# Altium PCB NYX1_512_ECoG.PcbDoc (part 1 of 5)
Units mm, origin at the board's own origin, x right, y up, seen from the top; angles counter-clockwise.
Board outline 46.64 x 13 mm, 4 copper layers (metal 2, via, metal1, electrodes), stack 0.007 mm thick; 9 components, 547 nets, 1871 pads, 0 vias.
Unrouted connection lines stored in the file: 652.
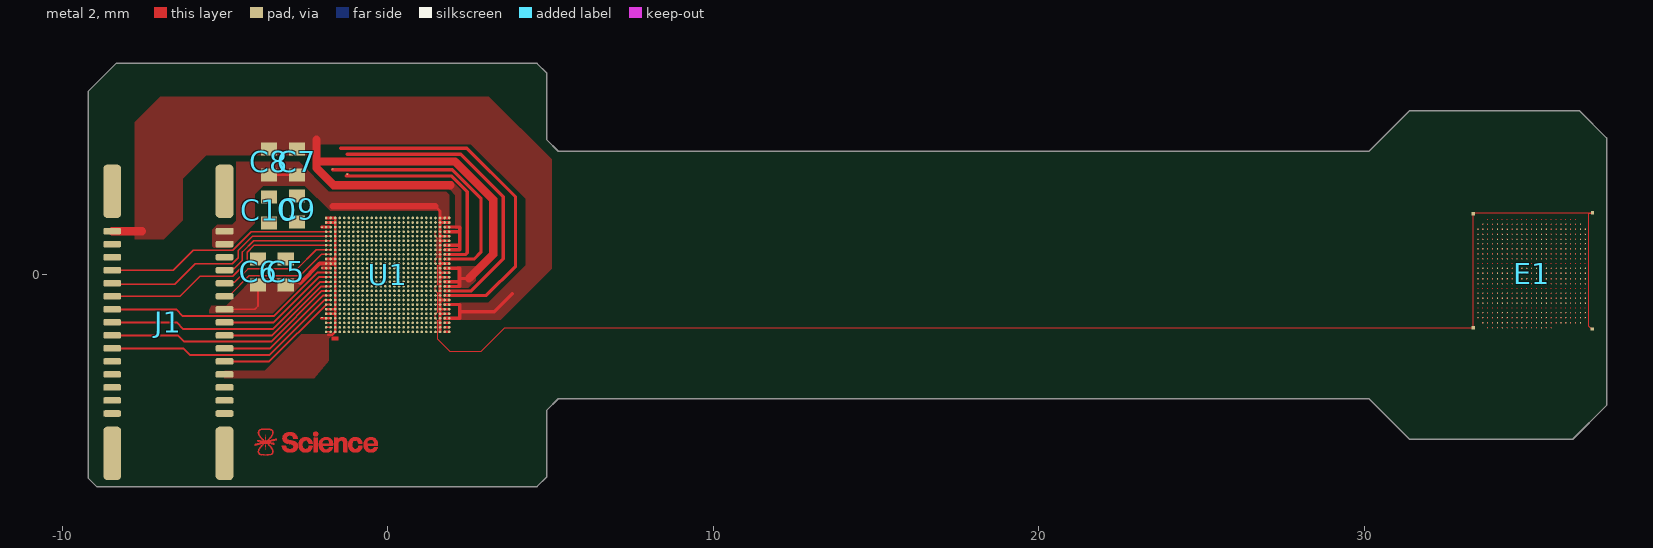
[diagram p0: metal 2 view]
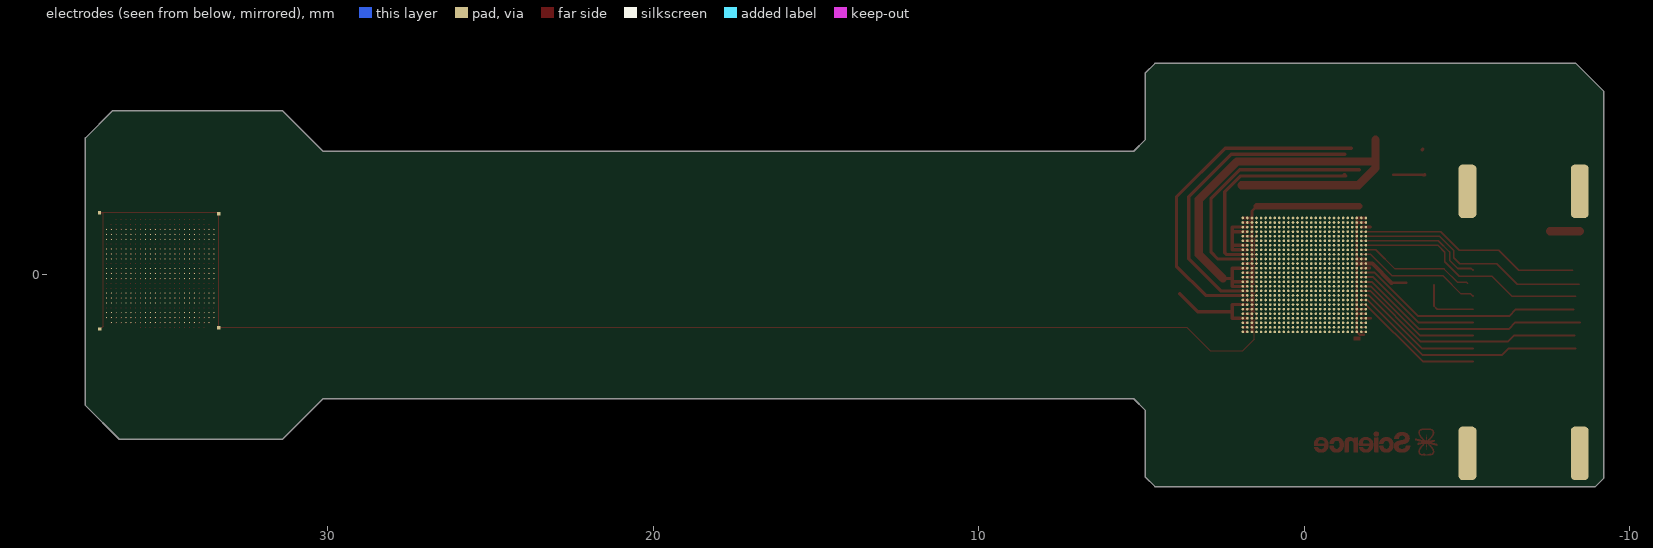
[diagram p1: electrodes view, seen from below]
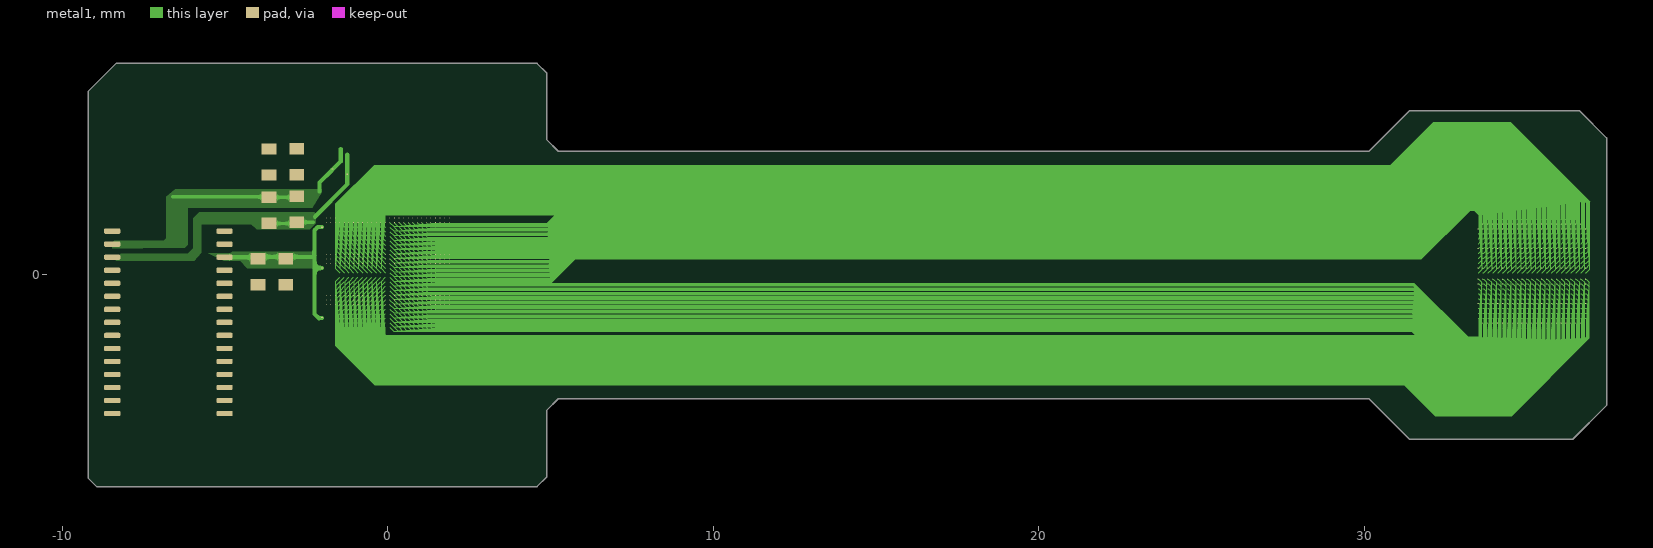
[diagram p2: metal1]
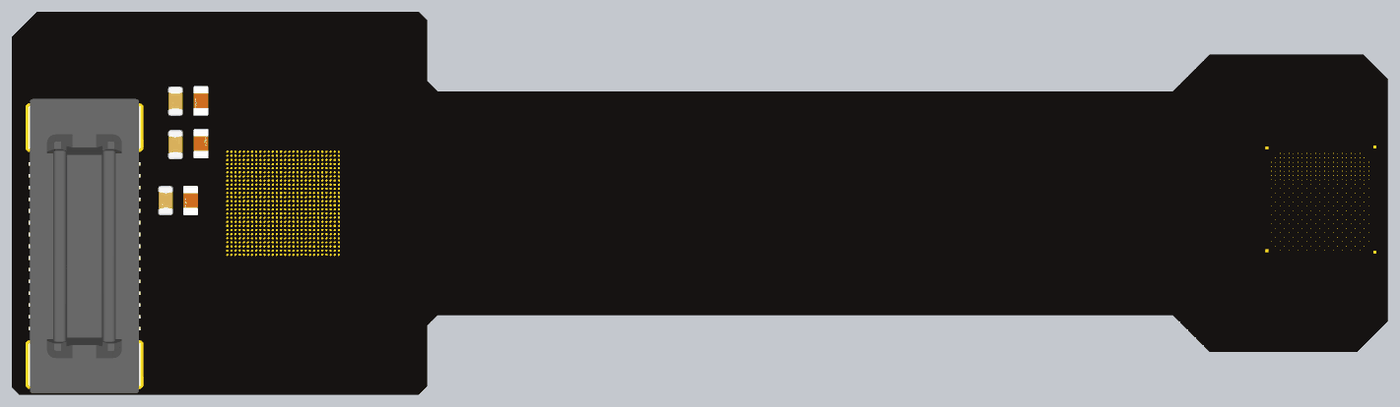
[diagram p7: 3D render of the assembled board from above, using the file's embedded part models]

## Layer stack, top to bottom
Top Solder: solder mask 0.003, Solder Resist, Dk 3.5
metal 2: signal copper 0.0002
Dielectric 2: prepreg 0.003, PP-006, Dk 4
via: signal copper 0.0002
Dielectric 1: dielectric 0.0001, FR-4, Dk 4
metal1: signal copper 0.0002
Dielectric 3: prepreg 0.003, PP-006, Dk 4
electrodes: signal copper 0.0002
Bottom Solder: solder mask 0.003, Solder Resist, Dk 3.5

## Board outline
-9.2,-6.239 -8.939,-6.5 4.592,-6.5 4.88,-6.212 4.88,-4.161 5.241,-3.8 30.141,-3.8 31.388,-5.047 36.4,-5.047 37.441,-4.006 37.441,4.21 36.604,5.047 31.388,5.047 30.141,3.8 5.241,3.8 4.88,4.161 4.88,6.212 4.592,6.5 -8.339,6.5 -9.2,5.639

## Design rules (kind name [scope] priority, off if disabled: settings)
BoardOutlineClearance [All] p1: gap=0.2 ignorepadtopadclearanceinfootprint=FALSE except(0: Arc-SplitContinuation Track-SplitContinuation SMDPad-SplitContinuation THPad-SplitContinuation Via-SplitContinuation Fill-SplitContinuation Poly-SplitContinuation Region-SplitContinuation Text-SplitContinuation)
Clearance [All] p1: gap=0.005 ignorepadtopadclearanceinfootprint=FALSE
ComponentClearance [All] p1: gap=0.254 collisioncheckmode=3 verticalgap=0.254 showdistances=FALSE donotcheckwithout3dbody=TRUE
MinimumSolderMaskSliver [All] p1: minsoldermaskwidth=0
PolygonConnect [All] p1: connectstyle=Direct reliefconductorwidth=0.254 reliefentries=4 polygonreliefangle="90 Angle" airgapwidth=0.254
RoutingVias [All] p1: holewidth=0.711 width=1.27 viastyle="Through Hole" minholewidth=0.711 minwidth=1.27 maxholewidth=0.711 maxwidth=1.27
SilkToSolderMaskClearance [IsPad] p1: minsilkscreentomaskgap=0 clearancetoexposedcopper=TRUE
SolderMaskExpansion [All] p1: expansion=0.102 istentingtop=FALSE
SupplyNets "Schematic Supply Nets_2" [InNet('DVSS')] p1: voltage=0.000
SupplyNets "Schematic Supply Nets_1" [InNet('DVSS_BOT')] p2: voltage=0.000
SupplyNets "Schematic Supply Nets" [InNet('VSSA')] p3: voltage=0.000
Width [All] p1: maxlimit=0.254 minlimit=0.005 preferedwidth=0.254 minimp=50.000000 maximp=50.000000 favimp=50.000000
27 further rules are at their usual default settings.

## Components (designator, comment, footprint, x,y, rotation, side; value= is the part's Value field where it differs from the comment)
C5 "GRT155R61E105KE01D" FP-GRT155-0_05-MFG -3.13,0.095 r270 top
C6 "CC0402KRX7R9BB104" FP-CC0402-MFG -3.98,0.095 r270 top value="100 nF"
C7 "GRT155R61E105KE01D" FP-GRT155-0_05-MFG -2.786,3.476 r270 top
C8 "CC0402KRX7R9BB104" FP-CC0402-MFG -3.644,3.47 r270 top value="100 nF"
C9 "GRT155R61E105KE01D" FP-GRT155-0_05-MFG -2.786,2.021 r90 top
C10 "CC0402KRX7R9BB104" FP-CC0402-MFG -3.644,1.992 r90 top value="100 nF"
E1 "512 Electrode Array MEA Layout" "512 Electrode Array-Footprint-1" 33.491,1.694 r0 top locked
J1 "BM54F3.0-30DP-0.4V_51_" BM54F3030DP04V51 -6.734,-1.454 r270 top locked
U1 "NYX512" NYX512_footprint 0,0.001 r270 top

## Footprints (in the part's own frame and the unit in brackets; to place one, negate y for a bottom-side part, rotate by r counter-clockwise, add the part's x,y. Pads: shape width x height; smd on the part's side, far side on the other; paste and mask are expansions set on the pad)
"512 Electrode Array-Footprint-1" [mm]
  rect 0.02x0.02 / inner rect 0x0 / far side rect 0.02x0.02 all layers, no hole mask-0.002: 1(0.3,0) 2(0.45,0) 3(0.6,0) 4(0.75,0) 5(0.9,0) 6(1.05,0) 7(1.2,0) 8(1.35,0) 9(1.5,0) 10(1.65,0) 11(1.8,0) 12(1.95,0) 13(2.1,0) 14(2.25,0) 15(2.4,0) 16(2.55,0) 17(2.7,0) 18(2.85,0) 19(3,0) 20(0.15,-0.15) 21(0.3,-0.15) 22(0.45,-0.15) 23(0.6,-0.15) 24(0.75,-0.15) 25(0.9,-0.15) 26(1.05,-0.15) 27(1.2,-0.15) 28(1.35,-0.15) 29(1.5,-0.15) 30(1.65,-0.15) 31(1.8,-0.15) 32(1.95,-0.15) 33(2.1,-0.15) 34(2.25,-0.15) 35(2.4,-0.15) 36(2.55,-0.15) 37(2.7,-0.15) 38(2.85,-0.15) 39(3,-0.15) 40(3.15,-0.15) 41(0,-0.3) 42(0.15,-0.3) 43(0.3,-0.3) 44(0.45,-0.3) 45(0.6,-0.3) 46(0.75,-0.3) 47(0.9,-0.3) 48(1.05,-0.3) 49(1.2,-0.3) 50(1.35,-0.3) 51(1.5,-0.3) 52(1.65,-0.3) 53(1.8,-0.3) 54(1.95,-0.3) 55(2.1,-0.3) 56(2.25,-0.3) 57(2.4,-0.3) 58(2.55,-0.3) 59(2.7,-0.3) 60(2.85,-0.3) 61(3,-0.3) 62(3.15,-0.3) 63(3.3,-0.3) 64(0,-0.45) 65(0.15,-0.45) 66(0.3,-0.45) 67(0.45,-0.45) 68(0.6,-0.45) 69(0.75,-0.45) 70(0.9,-0.45) 71(1.05,-0.45) 72(1.2,-0.45) 73(1.35,-0.45) 74(1.5,-0.45) 75(1.65,-0.45) 76(1.8,-0.45) 77(1.95,-0.45) 78(2.1,-0.45) 79(2.25,-0.45) 80(2.4,-0.45) 81(2.55,-0.45) 82(2.7,-0.45) 83(2.85,-0.45) 84(3,-0.45) 85(3.15,-0.45) 86(3.3,-0.45) 87(0,-0.6) 88(0.15,-0.6) 89(0.3,-0.6) 90(0.45,-0.6) 91(0.6,-0.6) 92(0.75,-0.6) 93(0.9,-0.6) 94(1.05,-0.6) 95(1.2,-0.6) 96(1.35,-0.6) 97(1.5,-0.6) 98(1.65,-0.6) 99(1.8,-0.6) 100(1.95,-0.6) 101(2.1,-0.6) 102(2.25,-0.6) 103(2.4,-0.6) 104(2.55,-0.6) 105(2.7,-0.6) 106(2.85,-0.6) 107(3,-0.6) 108(3.15,-0.6) 109(3.3,-0.6) 110(0,-0.75) 111(0.15,-0.75) 112(0.3,-0.75) 113(0.45,-0.75) 114(0.6,-0.75) 115(0.75,-0.75) 116(0.9,-0.75) 117(1.05,-0.75) 118(1.2,-0.75) 119(1.35,-0.75) 120(1.5,-0.75) 121(1.65,-0.75) 122(1.8,-0.75) 123(1.95,-0.75) 124(2.1,-0.75) 125(2.25,-0.75) 126(2.4,-0.75) 127(2.55,-0.75) 128(2.7,-0.75) 129(2.85,-0.75) 130(3,-0.75) 131(3.15,-0.75) 132(3.3,-0.75) 133(0,-0.9) 134(0.15,-0.9) 135(0.3,-0.9) 136(0.45,-0.9) 137(0.6,-0.9) 138(0.75,-0.9) 139(0.9,-0.9) 140(1.05,-0.9) 141(1.2,-0.9) 142(1.35,-0.9) 143(1.5,-0.9) 144(1.65,-0.9) 145(1.8,-0.9) 146(1.95,-0.9) 147(2.1,-0.9) 148(2.25,-0.9) 149(2.4,-0.9) 150(2.55,-0.9) 151(2.7,-0.9) 152(2.85,-0.9) 153(3,-0.9) 154(3.15,-0.9) 155(3.3,-0.9) 156(0,-1.05) 157(0.15,-1.05) 158(0.3,-1.05) 159(0.45,-1.05) 160(0.6,-1.05) 161(0.75,-1.05) 162(0.9,-1.05) 163(1.05,-1.05) 164(1.2,-1.05) 165(1.35,-1.05) 166(1.5,-1.05) 167(1.65,-1.05) 168(1.8,-1.05) 169(1.95,-1.05) 170(2.1,-1.05) 171(2.25,-1.05) 172(2.4,-1.05) 173(2.55,-1.05) 174(2.7,-1.05) 175(2.85,-1.05) 176(3,-1.05) 177(3.15,-1.05) 178(3.3,-1.05) 179(0,-1.2) 180(0.15,-1.2) 181(0.3,-1.2) 182(0.45,-1.2) 183(0.6,-1.2) 184(0.75,-1.2) 185(0.9,-1.2) 186(1.05,-1.2) 187(1.2,-1.2) 188(1.35,-1.2) 189(1.5,-1.2) 190(1.65,-1.2) 191(1.8,-1.2) 192(1.95,-1.2) 193(2.1,-1.2) 194(2.25,-1.2) 195(2.4,-1.2) 196(2.55,-1.2) 197(2.7,-1.2) 198(2.85,-1.2) 199(3,-1.2) 200(3.15,-1.2) 201(3.3,-1.2) 202(0,-1.35) 203(0.15,-1.35) 204(0.3,-1.35) 205(0.45,-1.35) 206(0.6,-1.35) 207(0.75,-1.35) 208(0.9,-1.35) 209(1.05,-1.35) 210(1.2,-1.35) 211(1.35,-1.35) 212(1.5,-1.35) 213(1.65,-1.35) 214(1.8,-1.35) 215(1.95,-1.35) 216(2.1,-1.35) 217(2.25,-1.35) 218(2.4,-1.35) 219(2.55,-1.35) 220(2.7,-1.35) 221(2.85,-1.35) 222(3,-1.35) 223(3.15,-1.35) 224(3.3,-1.35) 225(0,-1.5) 226(0.15,-1.5) 227(0.3,-1.5) 228(0.45,-1.5) 229(0.6,-1.5) 230(0.75,-1.5) 231(0.9,-1.5) 232(1.05,-1.5) 233(1.2,-1.5) 234(1.35,-1.5) 235(1.5,-1.5) 236(1.65,-1.5) 237(1.8,-1.5) 238(1.95,-1.5) 239(2.1,-1.5) 240(2.25,-1.5) 241(2.4,-1.5) 242(2.55,-1.5) 243(2.7,-1.5) 244(2.85,-1.5) 245(3,-1.5) 246(3.15,-1.5) 247(3.3,-1.5) 248(0,-1.65) 249(0.15,-1.65) 250(0.3,-1.65) 251(0.45,-1.65) 252(0.6,-1.65) 253(0.75,-1.65) 254(0.9,-1.65) 255(1.05,-1.65) 256(1.2,-1.65) 257(1.35,-1.65) 258(1.5,-1.65) 259(1.65,-1.65) 260(1.8,-1.65) 261(1.95,-1.65) 262(2.1,-1.65) 263(2.25,-1.65) 264(2.4,-1.65) 265(2.55,-1.65) 266(2.7,-1.65) 267(2.85,-1.65) 268(3,-1.65) 269(3.15,-1.65) 270(3.3,-1.65) 271(0,-1.8) 272(0.15,-1.8) 273(0.3,-1.8) 274(0.45,-1.8) 275(0.6,-1.8) 276(0.75,-1.8) 277(0.9,-1.8) 278(1.05,-1.8) 279(1.2,-1.8) 280(1.35,-1.8) 281(1.5,-1.8) 282(1.65,-1.8) 283(1.8,-1.8) 284(1.95,-1.8) 285(2.1,-1.8) 286(2.25,-1.8) 287(2.4,-1.8) 288(2.55,-1.8) 289(2.7,-1.8) 290(2.85,-1.8) 291(3,-1.8) 292(3.15,-1.8) 293(3.3,-1.8) 294(0,-1.95) 295(0.15,-1.95) 296(0.3,-1.95) 297(0.45,-1.95) 298(0.6,-1.95) 299(0.75,-1.95) 300(0.9,-1.95) 301(1.05,-1.95) 302(1.2,-1.95) 303(1.35,-1.95) 304(1.5,-1.95) 305(1.65,-1.95) 306(1.8,-1.95) 307(1.95,-1.95) 308(2.1,-1.95) 309(2.25,-1.95) 310(2.4,-1.95) 311(2.55,-1.95) 312(2.7,-1.95) 313(2.85,-1.95) 314(3,-1.95) 315(3.15,-1.95) 316(3.3,-1.95) 317(0,-2.1) 318(0.15,-2.1) 319(0.3,-2.1) 320(0.45,-2.1) 321(0.6,-2.1) 322(0.75,-2.1) 323(0.9,-2.1) 324(1.05,-2.1) 325(1.2,-2.1) 326(1.35,-2.1) 327(1.5,-2.1) 328(1.65,-2.1) 329(1.8,-2.1) 330(1.95,-2.1) 331(2.1,-2.1) 332(2.25,-2.1) 333(2.4,-2.1) 334(2.55,-2.1) 335(2.7,-2.1) 336(2.85,-2.1) 337(3,-2.1) 338(3.15,-2.1) 339(3.3,-2.1) 340(0,-2.25) 341(0.15,-2.25) 342(0.3,-2.25) 343(0.45,-2.25) 344(0.6,-2.25) 345(0.75,-2.25) 346(0.9,-2.25) 347(1.05,-2.25) 348(1.2,-2.25) 349(1.35,-2.25) 350(1.5,-2.25) 351(1.65,-2.25) 352(1.8,-2.25) 353(1.95,-2.25) 354(2.1,-2.25) 355(2.25,-2.25) 356(2.4,-2.25) 357(2.55,-2.25) 358(2.7,-2.25) 359(2.85,-2.25) 360(3,-2.25) 361(3.15,-2.25) 362(3.3,-2.25) 363(0,-2.4) 364(0.15,-2.4) 365(0.3,-2.4) 366(0.45,-2.4) 367(0.6,-2.4) 368(0.75,-2.4) 369(0.9,-2.4) 370(1.05,-2.4) 371(1.2,-2.4) 372(1.35,-2.4) 373(1.5,-2.4) 374(1.65,-2.4) 375(1.8,-2.4) 376(1.95,-2.4) 377(2.1,-2.4) 378(2.25,-2.4) 379(2.4,-2.4) 380(2.55,-2.4) 381(2.7,-2.4) 382(2.85,-2.4) 383(3,-2.4) 384(3.15,-2.4) 385(3.3,-2.4) 386(0,-2.55) 387(0.15,-2.55) 388(0.3,-2.55) 389(0.45,-2.55) 390(0.6,-2.55) 391(0.75,-2.55) 392(0.9,-2.55) 393(1.05,-2.55) 394(1.2,-2.55) 395(1.35,-2.55) 396(1.5,-2.55) 397(1.65,-2.55) 398(1.8,-2.55) 399(1.95,-2.55) 400(2.1,-2.55) 401(2.25,-2.55) 402(2.4,-2.55) 403(2.55,-2.55) 404(2.7,-2.55) 405(2.85,-2.55) 406(3,-2.55) 407(3.15,-2.55) 408(3.3,-2.55) 409(0,-2.7) 410(0.15,-2.7) 411(0.3,-2.7) 412(0.45,-2.7) 413(0.6,-2.7) 414(0.75,-2.7) 415(0.9,-2.7) 416(1.05,-2.7) 417(1.2,-2.7) 418(1.35,-2.7) 419(1.5,-2.7) 420(1.65,-2.7) 421(1.8,-2.7) 422(1.95,-2.7) 423(2.1,-2.7) 424(2.25,-2.7) 425(2.4,-2.7) 426(2.55,-2.7) 427(2.7,-2.7) 428(2.85,-2.7) 429(3,-2.7) 430(3.15,-2.7) 431(3.3,-2.7) 432(0,-2.85) 433(0.15,-2.85) 434(0.3,-2.85) 435(0.45,-2.85) 436(0.6,-2.85) 437(0.75,-2.85) 438(0.9,-2.85) 439(1.05,-2.85) 440(1.2,-2.85) 441(1.35,-2.85) 442(1.5,-2.85) 443(1.65,-2.85) 444(1.8,-2.85) 445(1.95,-2.85) 446(2.1,-2.85) 447(2.25,-2.85) 448(2.4,-2.85) 449(2.55,-2.85) 450(2.7,-2.85) 451(2.85,-2.85) 452(3,-2.85) 453(3.15,-2.85) 454(3.3,-2.85) 455(0,-3) 456(0.15,-3) 457(0.3,-3) 458(0.45,-3) 459(0.6,-3) 460(0.75,-3) 461(0.9,-3) 462(1.05,-3) 463(1.2,-3) 464(1.35,-3) 465(1.5,-3) 466(1.65,-3) 467(1.8,-3) 468(1.95,-3) 469(2.1,-3) 470(2.25,-3) 471(2.4,-3) 472(2.55,-3) 473(2.7,-3) 474(2.85,-3) 475(3,-3) 476(3.15,-3) 477(3.3,-3) 478(0.15,-3.15) 479(0.3,-3.15) 480(0.45,-3.15) 481(0.6,-3.15) 482(0.75,-3.15) 483(0.9,-3.15) 484(1.05,-3.15) 485(1.2,-3.15) 486(1.35,-3.15) 487(1.5,-3.15) 488(1.65,-3.15) 489(1.8,-3.15) 490(1.95,-3.15) 491(2.1,-3.15) 492(2.25,-3.15) 493(2.4,-3.15) 494(2.55,-3.15) 495(2.7,-3.15) 496(2.85,-3.15) 497(3,-3.15) 498(3.15,-3.15) 499(0.3,-3.3) 500(0.45,-3.3) 501(0.6,-3.3) 502(0.75,-3.3) 503(0.9,-3.3) 504(1.05,-3.3) 505(1.2,-3.3) 506(1.35,-3.3) 507(1.5,-3.3) 508(1.65,-3.3) 509(1.8,-3.3) 510(1.95,-3.3) 511(2.1,-3.3) 512(2.25,-3.3)
BM54F3030DP04V51 [mm]
  rrect50% 0.2x0.55 / inner rrect50% 0.16x0.5 / far side rrect50% 0x0 all layers, no hole paste+0 mask-0.015: 1(-2.8,-1.725) 2(-2.8,1.725) 3(-2.4,-1.725) 4(-2.4,1.725) 5(-2,-1.725) 6(-2,1.725) 7(-1.6,-1.725) 8(-1.6,1.725) 9(-1.2,-1.725) 10(-1.2,1.725) 11(-0.8,-1.725) 12(-0.8,1.725) 13(-0.4,-1.725) 14(-0.4,1.725) 15(0,-1.725) 16(0,1.725) 17(0.4,-1.725) 18(0.4,1.725) 19(0.8,-1.725) 20(0.8,1.725) 21(1.2,-1.725) 22(1.2,1.725) 23(1.6,-1.725) 24(1.6,1.725) 25(2,-1.725) 26(2,1.725) 27(2.4,-1.725) 28(2.4,1.725) 29(2.8,-1.725) 30(2.8,1.725)
  rrect50% 1.65x0.55 / inner rrect50% 0x0 / far side rrect50% 1.65x0.55 all layers, no hole paste+0 mask-0.015: 31(-4.025,-1.725) 32(-4.025,1.725) 33(4.025,-1.725) 34(4.025,1.725)
  body extent -4.99,-1.9 5.01,1.9, height 2.64
FP-CC0402-MFG [mm]
  rect 0.4x0.5 / inner rect 0.35x0.45 / far side rect 0x0 all layers, no hole paste+0 mask-0.03: 1(-0.4,0) 2(0.4,0)
  body extent -0.87,-0.48 0.87,0.48, height 0.25
FP-GRT155-0_05-MFG [mm]
  rect 0.4x0.5 / inner rect 0.35x0.45 / far side rect 0x0 all layers, no hole paste+0 mask-0.03: 1(-0.4,0) 2(0.4,0)
  body extent -0.7,-0.38 0.7,0.38, height 0.25
NYX512_footprint [mm]
  round 0.08 / inner round 0.009 / far side round 0.08 all layers, no hole mask+0: A1(-1.75,1.89) A2(-1.61,1.89) A3(-1.47,1.89) A4(-1.33,1.89) A5(-1.19,1.89) A6(-1.05,1.89) A7(-0.91,1.89) A8(-0.77,1.89) A9(-0.63,1.89) A10(-0.49,1.89) A11(-0.35,1.89) A12(-0.21,1.89) A13(-0.07,1.89) A14(0.07,1.89) A15(0.21,1.89) A16(0.35,1.89) A17(0.49,1.89) A18(0.63,1.89) A19(0.77,1.89) A20(0.91,1.89) A21(1.05,1.89) A22(1.19,1.89) A23(1.33,1.89) A24(1.47,1.89) A25(1.61,1.89) A26(1.75,1.89) AA2(-1.61,-0.91) AA3(-1.47,-0.91) AA4(-1.33,-0.91) AA5(-1.19,-0.91) AA6(-1.05,-0.91) AA7(-0.91,-0.91) AA8(-0.77,-0.91) AA9(-0.63,-0.91) AA10(-0.49,-0.91) AA11(-0.35,-0.91) AA12(-0.21,-0.91) AA13(-0.07,-0.91) AA14(0.07,-0.91) AA15(0.21,-0.91) AA16(0.35,-0.91) AA17(0.49,-0.91) AA18(0.63,-0.91) AA19(0.77,-0.91) AA20(0.91,-0.91) AA21(1.05,-0.91) AA22(1.19,-0.91) AA23(1.33,-0.91) AA24(1.47,-0.91) AA25(1.61,-0.91) AB2(-1.61,-1.05) AB3(-1.47,-1.05) AB4(-1.33,-1.05) AB5(-1.19,-1.05) AB6(-1.05,-1.05) AB7(-0.91,-1.05) AB8(-0.77,-1.05) AB9(-0.63,-1.05) AB10(-0.49,-1.05) AB11(-0.35,-1.05) AB12(-0.21,-1.05) AB13(-0.07,-1.05) AB14(0.07,-1.05) AB15(0.21,-1.05) AB16(0.35,-1.05) AB17(0.49,-1.05) AB18(0.63,-1.05) AB19(0.77,-1.05) AB20(0.91,-1.05) AB21(1.05,-1.05) AB22(1.19,-1.05) AB23(1.33,-1.05) AB24(1.47,-1.05) AB25(1.61,-1.05) AC2(-1.61,-1.19) AC3(-1.47,-1.19) AC4(-1.33,-1.19) AC5(-1.19,-1.19) AC6(-1.05,-1.19) AC7(-0.91,-1.19) AC8(-0.77,-1.19) AC9(-0.63,-1.19) AC10(-0.49,-1.19) AC11(-0.35,-1.19) AC12(-0.21,-1.19) AC13(-0.07,-1.19) AC14(0.07,-1.19) AC15(0.21,-1.19) AC16(0.35,-1.19) AC17(0.49,-1.19) AC18(0.63,-1.19) AC19(0.77,-1.19) AC20(0.91,-1.19) AC21(1.05,-1.19) AC22(1.19,-1.19) AC23(1.33,-1.19) AC24(1.47,-1.19) AC25(1.61,-1.19) AD2(-1.61,-1.33) AD3(-1.47,-1.33) AD4(-1.33,-1.33) AD5(-1.19,-1.33) AD6(-1.05,-1.33) AD7(-0.91,-1.33) AD8(-0.77,-1.33) AD9(-0.63,-1.33) AD10(-0.49,-1.33) AD11(-0.35,-1.33) AD12(-0.21,-1.33) AD13(-0.07,-1.33) AD14(0.07,-1.33) AD15(0.21,-1.33) AD16(0.35,-1.33) AD17(0.49,-1.33) AD18(0.63,-1.33) AD19(0.77,-1.33) AD20(0.91,-1.33) AD21(1.05,-1.33) AD22(1.19,-1.33) AD23(1.33,-1.33) AD24(1.47,-1.33) AD25(1.61,-1.33) AE2(-1.61,-1.47) AE3(-1.47,-1.47) AE4(-1.33,-1.47) AE5(-1.19,-1.47) AE6(-1.05,-1.47) AE7(-0.91,-1.47) AE8(-0.77,-1.47) AE9(-0.63,-1.47) AE10(-0.49,-1.47) AE11(-0.35,-1.47) AE12(-0.21,-1.47) AE13(-0.07,-1.47) AE14(0.07,-1.47) AE15(0.21,-1.47) AE16(0.35,-1.47) AE17(0.49,-1.47) AE18(0.63,-1.47) AE19(0.77,-1.47) AE20(0.91,-1.47) AE21(1.05,-1.47) AE22(1.19,-1.47) AE23(1.33,-1.47) AE24(1.47,-1.47) AE25(1.61,-1.47) AF1(-1.75,-1.61) AF2(-1.61,-1.61) AF3(-1.47,-1.61) AF4(-1.33,-1.61) AF5(-1.19,-1.61) AF6(-1.05,-1.61) AF7(-0.91,-1.61) AF8(-0.77,-1.61) AF9(-0.63,-1.61) AF10(-0.49,-1.61) AF11(-0.35,-1.61) AF12(-0.21,-1.61) AF13(-0.07,-1.61) AF14(0.07,-1.61) AF15(0.21,-1.61) AF16(0.35,-1.61) AF17(0.49,-1.61) AF18(0.63,-1.61) AF19(0.77,-1.61) AF20(0.91,-1.61) AF21(1.05,-1.61) AF22(1.19,-1.61) AF23(1.33,-1.61) AF24(1.47,-1.61) AF25(1.61,-1.61) AF26(1.75,-1.61) AG1(-1.75,-1.75) AG2(-1.61,-1.75) AG3(-1.47,-1.75) AG4(-1.33,-1.75) AG5(-1.19,-1.75) AG6(-1.05,-1.75) AG7(-0.91,-1.75) AG8(-0.77,-1.75) AG9(-0.63,-1.75) AG10(-0.49,-1.75) AG11(-0.35,-1.75) AG12(-0.21,-1.75) AG13(-0.07,-1.75) AG14(0.07,-1.75) AG15(0.21,-1.75) AG16(0.35,-1.75) AG17(0.49,-1.75) AG18(0.63,-1.75) AG19(0.77,-1.75) AG20(0.91,-1.75) AG21(1.05,-1.75) AG22(1.19,-1.75) AG23(1.33,-1.75) AG24(1.47,-1.75) AG25(1.61,-1.75) AG26(1.75,-1.75) AH1(-1.75,-1.89) AH2(-1.61,-1.89) AH3(-1.47,-1.89) AH4(-1.33,-1.89) AH5(-1.19,-1.89) AH6(-1.05,-1.89) AH7(-0.91,-1.89) AH8(-0.77,-1.89) AH9(-0.63,-1.89) AH10(-0.49,-1.89) AH11(-0.35,-1.89) AH12(-0.21,-1.89) AH13(-0.07,-1.89) AH14(0.07,-1.89) AH15(0.21,-1.89) AH16(0.35,-1.89) AH17(0.49,-1.89) AH18(0.63,-1.89) AH19(0.77,-1.89) AH20(0.91,-1.89) AH21(1.05,-1.89) AH22(1.19,-1.89) AH23(1.33,-1.89) AH24(1.47,-1.89) AH25(1.61,-1.89) AH26(1.75,-1.89) B1(-1.75,1.75) B2(-1.61,1.75) B3(-1.47,1.75) B4(-1.33,1.75) B5(-1.19,1.75) B6(-1.05,1.75) B7(-0.91,1.75) B8(-0.77,1.75) B9(-0.63,1.75) B10(-0.49,1.75) B11(-0.35,1.75) B12(-0.21,1.75) B13(-0.07,1.75) B14(0.07,1.75) B15(0.21,1.75) B16(0.35,1.75) B17(0.49,1.75) B18(0.63,1.75) B19(0.77,1.75) B20(0.91,1.75) B21(1.05,1.75) B22(1.19,1.75) B23(1.33,1.75) B24(1.47,1.75) B25(1.61,1.75) B26(1.75,1.75) C1(-1.75,1.61) C2(-1.61,1.61) C3(-1.47,1.61) C4(-1.33,1.61) C5(-1.19,1.61) C6(-1.05,1.61) C7(-0.91,1.61) C8(-0.77,1.61) C9(-0.63,1.61) C10(-0.49,1.61) C11(-0.35,1.61) C12(-0.21,1.61) C13(-0.07,1.61) C14(0.07,1.61) C15(0.21,1.61) C16(0.35,1.61) C17(0.49,1.61) C18(0.63,1.61) C19(0.77,1.61) C20(0.91,1.61) C21(1.05,1.61) C22(1.19,1.61) C23(1.33,1.61) C24(1.47,1.61) C25(1.61,1.61) C26(1.75,1.61) D1(-1.75,1.47) D2(-1.61,1.47) D3(-1.47,1.47) D4(-1.33,1.47) D5(-1.19,1.47) D6(-1.05,1.47) D7(-0.91,1.47) D8(-0.77,1.47) D9(-0.63,1.47) D10(-0.49,1.47) D11(-0.35,1.47) D12(-0.21,1.47) D13(-0.07,1.47) D14(0.07,1.47) D15(0.21,1.47) D16(0.35,1.47) D17(0.49,1.47) D18(0.63,1.47) D19(0.77,1.47) D20(0.91,1.47) D21(1.05,1.47) D22(1.19,1.47) D23(1.33,1.47) D24(1.47,1.47) D25(1.61,1.47) D26(1.75,1.47) E1(-1.75,1.33) E2(-1.61,1.33) E3(-1.47,1.33) E4(-1.33,1.33) E5(-1.19,1.33) E6(-1.05,1.33) E7(-0.91,1.33) E8(-0.77,1.33) E9(-0.63,1.33) E10(-0.49,1.33) E11(-0.35,1.33) E12(-0.21,1.33) E13(-0.07,1.33) E14(0.07,1.33) E15(0.21,1.33) E16(0.35,1.33) E17(0.49,1.33) E18(0.63,1.33) E19(0.77,1.33) E20(0.91,1.33) E21(1.05,1.33) E22(1.19,1.33) E23(1.33,1.33) E24(1.47,1.33) E25(1.61,1.33) E26(1.75,1.33) F1(-1.75,1.19) F2(-1.61,1.19) F3(-1.47,1.19) F4(-1.33,1.19) F5(-1.19,1.19) F6(-1.05,1.19) F7(-0.91,1.19) F8(-0.77,1.19) F9(-0.63,1.19) F10(-0.49,1.19) F11(-0.35,1.19) F12(-0.21,1.19) F13(-0.07,1.19) F14(0.07,1.19) F15(0.21,1.19) F16(0.35,1.19) F17(0.49,1.19) F18(0.63,1.19) F19(0.77,1.19) F20(0.91,1.19) F21(1.05,1.19) F22(1.19,1.19) F23(1.33,1.19) F24(1.47,1.19) F25(1.61,1.19) F26(1.75,1.19) G1(-1.75,1.05) G2(-1.61,1.05) G3(-1.47,1.05) G4(-1.33,1.05) G5(-1.19,1.05) G6(-1.05,1.05) G7(-0.91,1.05) G8(-0.77,1.05) G9(-0.63,1.05) G10(-0.49,1.05) G11(-0.35,1.05) G12(-0.21,1.05) G13(-0.07,1.05) G14(0.07,1.05) G15(0.21,1.05) G16(0.35,1.05) G17(0.49,1.05) G18(0.63,1.05) G19(0.77,1.05) G20(0.91,1.05) G21(1.05,1.05) G22(1.19,1.05) G23(1.33,1.05) G24(1.47,1.05) G25(1.61,1.05) G26(1.75,1.05) H1(-1.75,0.91) H2(-1.61,0.91) H3(-1.47,0.91) H4(-1.33,0.91) H5(-1.19,0.91) H6(-1.05,0.91) H7(-0.91,0.91) H8(-0.77,0.91) H9(-0.63,0.91) H10(-0.49,0.91) H11(-0.35,0.91) H12(-0.21,0.91) H13(-0.07,0.91) H14(0.07,0.91) H15(0.21,0.91) H16(0.35,0.91) H17(0.49,0.91) H18(0.63,0.91) H19(0.77,0.91) H20(0.91,0.91) H21(1.05,0.91) H22(1.19,0.91) H23(1.33,0.91) H24(1.47,0.91) H25(1.61,0.91) H26(1.75,0.91) J1(-1.75,0.77) J2(-1.61,0.77) J3(-1.47,0.77) J4(-1.33,0.77) J5(-1.19,0.77) J6(-1.05,0.77) J7(-0.91,0.77) J8(-0.77,0.77) J9(-0.63,0.77) J10(-0.49,0.77) J11(-0.35,0.77) J12(-0.21,0.77) J13(-0.07,0.77) J14(0.07,0.77) J15(0.21,0.77) J16(0.35,0.77) J17(0.49,0.77) J18(0.63,0.77) J19(0.77,0.77) J20(0.91,0.77) J21(1.05,0.77) J22(1.19,0.77) J23(1.33,0.77) J24(1.47,0.77) J25(1.61,0.77) J26(1.75,0.77) K1(-1.75,0.63) K2(-1.61,0.63) K3(-1.47,0.63) K4(-1.33,0.63) K5(-1.19,0.63) K6(-1.05,0.63) K7(-0.91,0.63) K8(-0.77,0.63) K9(-0.63,0.63) K10(-0.49,0.63) K11(-0.35,0.63) K12(-0.21,0.63) K13(-0.07,0.63) K14(0.07,0.63) K15(0.21,0.63) K16(0.35,0.63) K17(0.49,0.63) K18(0.63,0.63) K19(0.77,0.63) K20(0.91,0.63) K21(1.05,0.63) K22(1.19,0.63) K23(1.33,0.63) K24(1.47,0.63) K25(1.61,0.63) K26(1.75,0.63) L1(-1.75,0.49) L2(-1.61,0.49) L3(-1.47,0.49) L4(-1.33,0.49) L5(-1.19,0.49) L6(-1.05,0.49) L7(-0.91,0.49) L8(-0.77,0.49) L9(-0.63,0.49) L10(-0.49,0.49) L11(-0.35,0.49) L12(-0.21,0.49) L13(-0.07,0.49) L14(0.07,0.49) L15(0.21,0.49) L16(0.35,0.49) L17(0.49,0.49) L18(0.63,0.49) L19(0.77,0.49) L20(0.91,0.49) L21(1.05,0.49) L22(1.19,0.49) L23(1.33,0.49) L24(1.47,0.49) L25(1.61,0.49) L26(1.75,0.49) M1(-1.75,0.35) M2(-1.61,0.35) M3(-1.47,0.35) M4(-1.33,0.35) M5(-1.19,0.35) M6(-1.05,0.35) M7(-0.91,0.35) M8(-0.77,0.35) M9(-0.63,0.35) M10(-0.49,0.35) M11(-0.35,0.35) M12(-0.21,0.35) M13(-0.07,0.35) M14(0.07,0.35) M15(0.21,0.35) M16(0.35,0.35) M17(0.49,0.35) M18(0.63,0.35) M19(0.77,0.35) M20(0.91,0.35) M21(1.05,0.35) M22(1.19,0.35) M23(1.33,0.35) M24(1.47,0.35) M25(1.61,0.35) M26(1.75,0.35) N1(-1.75,0.21) N2(-1.61,0.21) N3(-1.47,0.21) N4(-1.33,0.21) N5(-1.19,0.21) N6(-1.05,0.21) N7(-0.91,0.21) N8(-0.77,0.21) N9(-0.63,0.21) N10(-0.49,0.21) N11(-0.35,0.21) N12(-0.21,0.21) N13(-0.07,0.21) N14(0.07,0.21) N15(0.21,0.21) N16(0.35,0.21) N17(0.49,0.21) N18(0.63,0.21) N19(0.77,0.21) N20(0.91,0.21) N21(1.05,0.21) N22(1.19,0.21) N23(1.33,0.21) N24(1.47,0.21) N25(1.61,0.21) N26(1.75,0.21) P1(-1.75,0.07) P2(-1.61,0.07) P3(-1.47,0.07) P4(-1.33,0.07) P5(-1.19,0.07) P6(-1.05,0.07) P7(-0.91,0.07) P8(-0.77,0.07) P9(-0.63,0.07) P10(-0.49,0.07) P11(-0.35,0.07) P12(-0.21,0.07) P13(-0.07,0.07) P14(0.07,0.07) P15(0.21,0.07) P16(0.35,0.07) P17(0.49,0.07) P18(0.63,0.07) P19(0.77,0.07) P20(0.91,0.07) P21(1.05,0.07) P22(1.19,0.07) P23(1.33,0.07) P24(1.47,0.07) P25(1.61,0.07) P26(1.75,0.07) R2(-1.61,-0.07) R3(-1.47,-0.07) R4(-1.33,-0.07) R5(-1.19,-0.07) R6(-1.05,-0.07) R7(-0.91,-0.07) R8(-0.77,-0.07) R9(-0.63,-0.07) R10(-0.49,-0.07) R11(-0.35,-0.07) R12(-0.21,-0.07) R13(-0.07,-0.07) R14(0.07,-0.07) R15(0.21,-0.07) R16(0.35,-0.07) R17(0.49,-0.07) R18(0.63,-0.07) R19(0.77,-0.07) R20(0.91,-0.07) R21(1.05,-0.07) R22(1.19,-0.07) R23(1.33,-0.07) R24(1.47,-0.07) R25(1.61,-0.07) T2(-1.61,-0.21) T3(-1.47,-0.21) T4(-1.33,-0.21) T5(-1.19,-0.21) T6(-1.05,-0.21) T7(-0.91,-0.21) T8(-0.77,-0.21) T9(-0.63,-0.21) T10(-0.49,-0.21) T11(-0.35,-0.21) T12(-0.21,-0.21) T13(-0.07,-0.21) T14(0.07,-0.21) T15(0.21,-0.21) T16(0.35,-0.21) T17(0.49,-0.21) T18(0.63,-0.21) T19(0.77,-0.21) T20(0.91,-0.21) T21(1.05,-0.21) T22(1.19,-0.21) T23(1.33,-0.21) T24(1.47,-0.21) T25(1.61,-0.21) U2(-1.61,-0.35) U3(-1.47,-0.35) U4(-1.33,-0.35) U5(-1.19,-0.35) U6(-1.05,-0.35) U7(-0.91,-0.35) U8(-0.77,-0.35) U9(-0.63,-0.35) U10(-0.49,-0.35) U11(-0.35,-0.35) U12(-0.21,-0.35) U13(-0.07,-0.35) U14(0.07,-0.35) U15(0.21,-0.35) U16(0.35,-0.35) U17(0.49,-0.35) U18(0.63,-0.35) U19(0.77,-0.35) U20(0.91,-0.35) U21(1.05,-0.35) U22(1.19,-0.35) U23(1.33,-0.35) U24(1.47,-0.35) U25(1.61,-0.35) V2(-1.61,-0.49) V3(-1.47,-0.49) V4(-1.33,-0.49) V5(-1.19,-0.49) V6(-1.05,-0.49) V7(-0.91,-0.49) V8(-0.77,-0.49) V9(-0.63,-0.49) V10(-0.49,-0.49) V11(-0.35,-0.49) V12(-0.21,-0.49) V13(-0.07,-0.49) V14(0.07,-0.49) V15(0.21,-0.49) V16(0.35,-0.49) V17(0.49,-0.49) V18(0.63,-0.49) V19(0.77,-0.49) V20(0.91,-0.49) V21(1.05,-0.49) V22(1.19,-0.49) V23(1.33,-0.49) V24(1.47,-0.49) V25(1.61,-0.49) W2(-1.61,-0.63) W3(-1.47,-0.63) W4(-1.33,-0.63) W5(-1.19,-0.63) W6(-1.05,-0.63) W7(-0.91,-0.63) W8(-0.77,-0.63) W9(-0.63,-0.63) W10(-0.49,-0.63) W11(-0.35,-0.63) W12(-0.21,-0.63) W13(-0.07,-0.63) W14(0.07,-0.63) W15(0.21,-0.63) W16(0.35,-0.63) W17(0.49,-0.63) W18(0.63,-0.63) W19(0.77,-0.63) W20(0.91,-0.63) W21(1.05,-0.63) W22(1.19,-0.63) W23(1.33,-0.63) W24(1.47,-0.63) W25(1.61,-0.63) Y2(-1.61,-0.77) Y3(-1.47,-0.77) Y4(-1.33,-0.77) Y5(-1.19,-0.77) Y6(-1.05,-0.77) Y7(-0.91,-0.77) Y8(-0.77,-0.77) Y9(-0.63,-0.77) Y10(-0.49,-0.77) Y11(-0.35,-0.77) Y12(-0.21,-0.77) Y13(-0.07,-0.77) Y14(0.07,-0.77) Y15(0.21,-0.77) Y16(0.35,-0.77) Y17(0.49,-0.77) Y18(0.63,-0.77) Y19(0.77,-0.77) Y20(0.91,-0.77) Y21(1.05,-0.77) Y22(1.19,-0.77) Y23(1.33,-0.77) Y24(1.47,-0.77) Y25(1.61,-0.77)
  round 0.08 / inner round 0 / far side round 0.08 all layers, no hole mask+0: AA1(-1.75,-0.91) AA26(1.75,-0.91) AB1(-1.75,-1.05) AB26(1.75,-1.05) AC1(-1.75,-1.19) AC26(1.75,-1.19) AD1(-1.75,-1.33) AD26(1.75,-1.33) AE1(-1.75,-1.47) AE26(1.75,-1.47) R1(-1.75,-0.07) R26(1.75,-0.07) T1(-1.75,-0.21) T26(1.75,-0.21) U1(-1.75,-0.35) U26(1.75,-0.35) V1(-1.75,-0.49) V26(1.75,-0.49) W1(-1.75,-0.63) W26(1.75,-0.63) Y1(-1.75,-0.77) Y26(1.75,-0.77)
  metal 2 region: 1.899,-1.515 1.999,-1.515 1.999,-1.715 1.899,-1.715
  body extent -2.1,-2.1 2.1,2.1, height 0.15

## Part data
C5 C7 C9: library part CMP-06035-018811-1, "Multi-Layer Ceramic Capacitor 1uF 25V X5R ±10% 0402 Paper T/R", Capacitance=1uF, Case Code (Imperial)=0402, Case Code (Metric)=1005, Dielectric=X5R, Max Operating Temperature=85°C, Min Operating Temperature=-55°C, Ratings=AEC-Q200, Tolerance=10%, Voltage Rating=25V
C6 C8 C10: library part CMP-03422-001010-1, "CAP CER 0.1UF 50V X7R 0402", Capacitance="100 nF", Manufacturer=YAGEO, Package=CC0402, Temperature="-55°C to +125°C", Temperature Characteristic=X7R, Temperature Coefficient=30ppm/°C, Temperature Range High=+125°C, Temperature Range Low=-55°C, Tolerance=0.1, Voltage Rating="50 V"
E1: library part CMP-00022-1, "20x20 um electrodes, 150 um pitch"
J1: library part CMP-290-000006-2, "Board to Board & Mezzanine Connectors Plug", Manufacturer_Name=Hirose, Manufacturer_Part_Number=BM54F3.0-30DP-0.4V(51)
U1: library part CMP-031-00061-2, "ASIC01 512 electrode neural recording IC", MPN=ASIC01(SCIENCE), Package=micropillar-724

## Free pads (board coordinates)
  rect 0.008x0.008 on Mech1: 27(33.866,1.619)
  rect 0.1x0.1 / inner round 0 / far side rect 0.1x0.1 all layers, no hole mask-0.01: 28(33.341,-1.619) 28(33.341,1.877) 28(36.997,-1.656) 28(37.005,1.908)
  round 0.009 / inner round 0.009 / far side round 0 all layers, no hole mask+0.102: 34(-2.03,-1.344) 34(-2.03,-1.326) 34(-2.03,-1.308) 34(-2.03,0.196) 34(-2.03,0.214) 34(-2.03,0.232) 34(-2.03,1.456) 34(-2.03,1.474) 34(-2.03,1.492) 34(-2.012,-1.344) 34(-2.012,-1.326) 34(-2.012,-1.308) 34(-2.012,0.196) 34(-2.012,0.214) 34(-2.012,0.232) 34(-2.012,1.456) 34(-2.012,1.474) 34(-2.012,1.492) 34(-1.994,-1.344) 34(-1.994,-1.326) 34(-1.994,-1.308) 34(-1.994,0.196) 34(-1.994,0.214) 34(-1.994,0.232) 34(-1.994,1.456) 34(-1.994,1.474) 34(-1.994,1.492) 34(-1.715,3.217) 34(-1.715,3.235) 34(-1.715,3.253) 34(-1.697,3.217) 34(-1.697,3.235) 34(-1.697,3.253) 34(-1.679,3.217) 34(-1.679,3.235) 34(-1.679,3.253) 34(-1.459,3.873) 34(-1.459,3.891) 34(-1.459,3.909) 34(-1.441,3.873) 34(-1.441,3.891) 34(-1.441,3.909) 34(-1.423,3.873) 34(-1.423,3.891) 34(-1.423,3.909) 34(-1.259,3.066) 34(-1.259,3.084) 34(-1.259,3.102) 34(-1.259,3.691) 34(-1.259,3.709) 34(-1.259,3.727) 34(-1.241,3.066) 34(-1.241,3.084) 34(-1.241,3.102) 34(-1.241,3.691) 34(-1.241,3.709) 34(-1.241,3.727) 34(-1.223,3.066) 34(-1.223,3.084) 34(-1.223,3.102) 34(-1.223,3.691) 34(-1.223,3.709) 34(-1.223,3.727)
  round 0.015 / inner round 0.009 / far side round 0 all layers, no hole mask+0.102: 34(33.491,-1.325) 34(33.491,-1.175) 34(33.491,-1.025) 34(33.491,-0.875) 34(33.491,-0.725) 34(33.491,-0.575) 34(33.491,-0.425) 34(33.491,-0.275) 34(33.491,-0.125) 34(33.491,0.064) 34(33.491,0.214) 34(33.491,0.364) 34(33.491,0.514) 34(33.491,0.664) 34(33.491,0.814) 34(33.491,0.964) 34(33.491,1.114) 34(33.491,1.264) 34(33.491,1.414) 34(33.641,-1.475) 34(33.641,-1.325) 34(33.641,-1.175) 34(33.641,-1.025) 34(33.641,-0.875) 34(33.641,-0.725) 34(33.641,-0.575) 34(33.641,-0.425) 34(33.641,-0.275) 34(33.641,-0.125) 34(33.641,0.064) 34(33.641,0.214) 34(33.641,0.364) 34(33.641,0.514) 34(33.641,0.664) 34(33.641,0.814) 34(33.641,0.964) 34(33.641,1.114) 34(33.641,1.264) 34(33.641,1.414) 34(33.641,1.564) 34(33.791,-1.625) 34(33.791,-1.475) 34(33.791,-1.325) 34(33.791,-1.175) 34(33.791,-1.025) 34(33.791,-0.875) 34(33.791,-0.725) 34(33.791,-0.575) 34(33.791,-0.425) 34(33.791,-0.275) 34(33.791,-0.125) 34(33.791,0.064) 34(33.791,0.214) 34(33.791,0.364) 34(33.791,0.514) 34(33.791,0.664) 34(33.791,0.814) 34(33.791,0.964) 34(33.791,1.114) 34(33.791,1.264) 34(33.791,1.414) 34(33.791,1.564) 34(33.791,1.714) 34(33.941,-1.625) 34(33.941,-1.475) 34(33.941,-1.325) 34(33.941,-1.175) 34(33.941,-1.025) 34(33.941,-0.875) 34(33.941,-0.725) 34(33.941,-0.575) 34(33.941,-0.425) 34(33.941,-0.275) 34(33.941,-0.125) 34(33.941,0.064) 34(33.941,0.214) 34(33.941,0.364) 34(33.941,0.514) 34(33.941,0.664) 34(33.941,0.814) 34(33.941,0.964) 34(33.941,1.114) 34(33.941,1.264) 34(33.941,1.414) 34(33.941,1.564) 34(33.941,1.714) 34(34.091,-1.625) 34(34.091,-1.475) 34(34.091,-1.325) 34(34.091,-1.175) 34(34.091,-1.025) 34(34.091,-0.875) 34(34.091,-0.725) 34(34.091,-0.575) 34(34.091,-0.425) 34(34.091,-0.275) 34(34.091,-0.125) 34(34.091,0.064) 34(34.091,0.214) 34(34.091,0.364) 34(34.091,0.514) 34(34.091,0.664) 34(34.091,0.814) 34(34.091,0.964) 34(34.091,1.114) 34(34.091,1.264) 34(34.091,1.414) 34(34.091,1.564) 34(34.091,1.714) 34(34.241,-1.475) 34(34.241,-1.325) 34(34.241,-1.175) 34(34.241,-1.025) 34(34.241,-0.875) 34(34.241,-0.725) 34(34.241,-0.575) 34(34.241,-0.425) 34(34.241,-0.275) 34(34.241,-0.125) 34(34.241,0.064) 34(34.241,0.214) 34(34.241,0.364) 34(34.241,0.514) 34(34.241,0.664) 34(34.241,0.814) 34(34.241,0.964) 34(34.241,1.414) 34(34.241,-1.625) 34(34.241,1.114) 34(34.241,1.264) 34(34.241,1.564) 34(34.241,1.714) 34(34.391,-1.475) 34(34.391,-1.625) 34(34.391,-1.325) 34(34.391,-1.175) 34(34.391,-1.025) 34(34.391,-0.875) 34(34.391,-0.725) 34(34.391,-0.575) 34(34.391,-0.425) 34(34.391,-0.275) 34(34.391,-0.125) 34(34.391,0.064) 34(34.391,0.214) 34(34.391,0.364) 34(34.391,0.514) 34(34.391,0.664) 34(34.391,0.814) 34(34.391,0.964) 34(34.391,1.114) 34(34.391,1.264) 34(34.391,1.414) 34(34.391,1.564) 34(34.391,1.714) 34(34.541,-1.625) 34(34.541,-1.475) 34(34.541,-1.325) 34(34.541,-1.175) 34(34.541,-1.025) 34(34.541,-0.875) 34(34.541,-0.725) 34(34.541,-0.575) 34(34.541,-0.425) 34(34.541,-0.275) 34(34.541,-0.125) 34(34.541,0.064) 34(34.541,0.214) 34(34.541,0.364) 34(34.541,0.514) 34(34.541,0.664) 34(34.541,0.814) 34(34.541,0.964) 34(34.541,1.114) 34(34.541,1.264) 34(34.541,1.414) 34(34.541,1.564) 34(34.541,1.714) 34(34.691,-1.625) 34(34.691,-1.475) 34(34.691,-1.325) 34(34.691,-1.175) 34(34.691,-1.025) 34(34.691,-0.875) 34(34.691,-0.725) 34(34.691,-0.575) 34(34.691,-0.425) 34(34.691,-0.275) 34(34.691,-0.125) 34(34.691,0.064) 34(34.691,0.214) 34(34.691,0.364) 34(34.691,0.514) 34(34.691,0.664) 34(34.691,0.814) 34(34.691,0.964) 34(34.691,1.114) 34(34.691,1.264) 34(34.691,1.414) 34(34.691,1.564) 34(34.691,1.714) 34(34.841,-1.625) 34(34.841,-1.475) 34(34.841,-1.325) 34(34.841,-1.175) 34(34.841,-1.025) 34(34.841,-0.875) 34(34.841,-0.725) 34(34.841,-0.575) 34(34.841,-0.425) 34(34.841,-0.275) 34(34.841,-0.125) 34(34.841,0.064) 34(34.841,0.214) 34(34.841,0.364) 34(34.841,0.514) 34(34.841,0.664) 34(34.841,0.814) 34(34.841,0.964) 34(34.841,1.114) 34(34.841,1.264) 34(34.841,1.414) 34(34.841,1.564) 34(34.841,1.714) 34(34.991,-1.625) 34(34.991,-1.475) 34(34.991,-1.325) 34(34.991,-1.175) 34(34.991,-1.025) 34(34.991,-0.875) 34(34.991,-0.725) 34(34.991,-0.575) 34(34.991,-0.425) 34(34.991,-0.275) 34(34.991,-0.125) 34(34.991,0.064) 34(34.991,0.214) 34(34.991,0.364) 34(34.991,0.514) 34(34.991,0.664) 34(34.991,0.814) 34(34.991,0.964) 34(34.991,1.114) 34(34.991,1.264) 34(34.991,1.414) 34(34.991,1.564) 34(34.991,1.714) 34(35.141,-1.625) 34(35.141,-1.475) 34(35.141,-1.325) 34(35.141,-1.175) 34(35.141,-1.025) 34(35.141,-0.875) 34(35.141,-0.725) 34(35.141,-0.575) 34(35.141,-0.425) 34(35.141,-0.275) 34(35.141,-0.125) 34(35.141,0.064) 34(35.141,0.214) 34(35.141,0.364) 34(35.141,0.514) 34(35.141,0.664) 34(35.141,0.814) 34(35.141,0.964) 34(35.141,1.114) 34(35.141,1.264) 34(35.141,1.414) 34(35.141,1.564) 34(35.141,1.714) 34(35.291,-1.625) 34(35.291,-1.475) 34(35.291,-1.325) 34(35.291,-1.175) 34(35.291,-1.025) 34(35.291,-0.875) 34(35.291,-0.725) 34(35.291,-0.575) 34(35.291,-0.425) 34(35.291,-0.275) 34(35.291,-0.125) 34(35.291,0.064) 34(35.291,0.214) 34(35.291,0.364) 34(35.291,0.514) 34(35.291,0.664) 34(35.291,0.814) 34(35.291,0.964) 34(35.291,1.114) 34(35.291,1.264) 34(35.291,1.414) 34(35.291,1.564) 34(35.291,1.714) 34(35.441,-1.475) 34(35.441,-1.325) 34(35.441,-1.175) 34(35.441,-1.025) 34(35.441,-0.875) 34(35.441,-0.725) 34(35.441,-0.575) 34(35.441,-0.425) 34(35.441,-0.275) 34(35.441,-0.125) 34(35.441,0.064) 34(35.441,0.214) 34(35.441,0.364) 34(35.441,0.514) 34(35.441,0.664) 34(35.441,0.814) 34(35.441,0.964) 34(35.441,1.414) 34(35.441,-1.625) 34(35.441,1.114) 34(35.441,1.264) 34(35.441,1.564) 34(35.441,1.714) 34(35.591,-1.475) 34(35.591,-1.625) 34(35.591,-1.325) 34(35.591,-1.175) 34(35.591,-1.025) 34(35.591,-0.875) 34(35.591,-0.725) 34(35.591,-0.575) 34(35.591,-0.425) 34(35.591,-0.275) 34(35.591,-0.125) 34(35.591,0.064) 34(35.591,0.214) 34(35.591,0.364) 34(35.591,0.514) 34(35.591,0.664) 34(35.591,0.814) 34(35.591,0.964) 34(35.591,1.114) 34(35.591,1.264) 34(35.591,1.414) 34(35.591,1.564) 34(35.591,1.714) 34(35.741,-1.625) 34(35.741,-1.475) 34(35.741,-1.325) 34(35.741,-1.175) 34(35.741,-1.025) 34(35.741,-0.875) 34(35.741,-0.725) 34(35.741,-0.575) 34(35.741,-0.425) 34(35.741,-0.275) 34(35.741,-0.125) 34(35.741,0.064) 34(35.741,0.214) 34(35.741,0.364) 34(35.741,0.514) 34(35.741,0.664) 34(35.741,0.814) 34(35.741,0.964) 34(35.741,1.114) 34(35.741,1.264) 34(35.741,1.414) 34(35.741,1.564) 34(35.741,1.714) 34(35.891,-1.475) 34(35.891,-1.325) 34(35.891,-1.175) 34(35.891,-1.025) 34(35.891,-0.875) 34(35.891,-0.725) 34(35.891,-0.575) 34(35.891,-0.425) 34(35.891,-0.275) 34(35.891,-0.125) 34(35.891,0.064) 34(35.891,0.214) 34(35.891,0.364) 34(35.891,0.514) 34(35.891,0.664) 34(35.891,0.814) 34(35.891,0.964) 34(35.891,1.114) 34(35.891,1.264) 34(35.891,1.414) 34(35.891,1.564) 34(35.891,1.714) 34(36.041,-1.475) 34(36.041,-1.325) 34(36.041,-1.175) 34(36.041,-1.025) 34(36.041,-0.875) 34(36.041,-0.725) 34(36.041,-0.575) 34(36.041,-0.425) 34(36.041,-0.275) 34(36.041,-0.125) 34(36.041,0.064) 34(36.041,0.214) 34(36.041,0.364) 34(36.041,0.514) 34(36.041,0.664) 34(36.041,0.814) 34(36.041,0.964) 34(36.041,1.114) 34(36.041,1.264) 34(36.041,1.414) 34(36.041,1.564) 34(36.041,1.714) 34(36.191,-1.475) 34(36.191,-1.325) 34(36.191,-1.175) 34(36.191,-1.025) 34(36.191,-0.875) 34(36.191,-0.725) 34(36.191,-0.575) 34(36.191,-0.425) 34(36.191,-0.275) 34(36.191,-0.125) 34(36.191,0.064) 34(36.191,0.214) 34(36.191,0.364) 34(36.191,0.514) 34(36.191,0.664) 34(36.191,0.814) 34(36.191,0.964) 34(36.191,1.114) 34(36.191,1.264) 34(36.191,1.414) 34(36.191,1.564) 34(36.191,1.714) 34(36.341,-1.475) 34(36.341,-1.325) 34(36.341,-1.175) 34(36.341,-1.025) 34(36.341,-0.875) 34(36.341,-0.725) 34(36.341,-0.575) 34(36.341,-0.425) 34(36.341,-0.275) 34(36.341,-0.125) 34(36.341,0.064) 34(36.341,0.214) 34(36.341,0.364) 34(36.341,0.514) 34(36.341,0.664) 34(36.341,0.814) 34(36.341,0.964) 34(36.341,1.114) 34(36.341,1.264) 34(36.341,1.414) 34(36.341,1.564) 34(36.341,1.714) 34(36.491,-1.475) 34(36.491,-1.325) 34(36.491,-1.175) 34(36.491,-1.025) 34(36.491,-0.875) 34(36.491,-0.725) 34(36.491,-0.575) 34(36.491,-0.425) 34(36.491,-0.275) 34(36.491,-0.125) 34(36.491,0.064) 34(36.491,0.214) 34(36.491,0.364) 34(36.491,0.514) 34(36.491,0.664) 34(36.491,0.814) 34(36.491,0.964) 34(36.491,1.114) 34(36.491,1.264) 34(36.491,1.414) 34(36.491,1.564) 34(36.491,1.714) 34(36.641,-1.475) 34(36.641,-1.325) 34(36.641,-1.175) 34(36.641,-1.025) 34(36.641,-0.875) 34(36.641,-0.725) 34(36.641,-0.575) 34(36.641,-0.425) 34(36.641,-0.275) 34(36.641,-0.125) 34(36.641,0.064) 34(36.641,0.214) 34(36.641,0.364) 34(36.641,0.514) 34(36.641,0.664) 34(36.641,0.814) 34(36.641,0.964) 34(36.641,1.414) 34(36.641,1.114) 34(36.641,1.264) 34(36.641,1.564) 34(36.791,-1.325) 34(36.791,-1.175) 34(36.791,-1.025) 34(36.791,-0.875) 34(36.791,-0.725) 34(36.791,-0.575) 34(36.791,-0.425) 34(36.791,-0.275) 34(36.791,-0.125) 34(36.791,0.064) 34(36.791,0.214) 34(36.791,0.364) 34(36.791,0.514) 34(36.791,0.664) 34(36.791,0.814) 34(36.791,0.964) 34(36.791,1.114) 34(36.791,1.264) 34(36.791,1.414)
  rect 0.02x0.02 / inner round 0 / far side rect 0.02x0.02 all layers, no hole mask-0.002: 37(35.891,-1.606) 37(36.041,-1.606) 37(36.191,-1.606) 37(36.341,-1.606) 37(36.491,-1.606)

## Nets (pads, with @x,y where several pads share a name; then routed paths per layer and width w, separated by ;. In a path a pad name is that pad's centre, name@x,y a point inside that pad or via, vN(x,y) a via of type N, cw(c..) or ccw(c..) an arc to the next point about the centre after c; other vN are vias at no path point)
ASIC1_CLK: J1.12 U1.AG9 U1.AH9 | length 4
  metal 2 w0.05: J1.12@-5.184,-0.656 -5.11,-0.582 -4.813,-0.582 -4.256,-0.024 -2.694,-0.024 -2.038,0.631 U1.AH9@-1.89,0.631 U1.AG9@-1.75,0.631
ASIC1_CS: J1.7 U1.AG4 U1.AH4 | length 7
  metal 2 w0.05: J1.7@-8.236,0.144 -6.588,0.144 -5.973,0.759 -4.757,0.759 -4.185,1.331 U1.AH4@-1.89,1.331 U1.AG4@-1.75,1.331
ASIC1_DATA0: J1.13 U1.AG13 U1.AH13 | length 7.2
  metal 2 w0.06: J1.13@-8.263,-1.056 -6.496,-1.056 -6.287,-1.265 -3.491,-1.265 -2.155,0.071 U1.AH13@-1.89,0.071 U1.AG13@-1.75,0.071
ASIC1_DATA1: J1.15 U1.AG15 U1.AH15 | length 7.4
  metal 2 w0.06: J1.15@-8.459,-1.456 -6.48,-1.456 -6.272,-1.664 -3.529,-1.664 -2.074,-0.209 U1.AH15@-1.89,-0.209 U1.AG15@-1.75,-0.209
ASIC1_DATA2: J1.17 U1.AG17 U1.AH17 | length 7.3
  metal 2 w0.06: J1.17@-8.291,-1.856 -6.443,-1.856 -6.25,-2.048 -3.579,-2.048 -2.02,-0.489 U1.AH17@-1.89,-0.489 U1.AG17@-1.75,-0.489
ASIC1_DATA3: J1.19 U1.AG19 U1.AH19 | length 7.3
  metal 2 w0.06: J1.19@-8.321,-2.256 -6.271,-2.256 -6.072,-2.455 -3.626,-2.455 -1.946,-0.774 U1.AH19@-1.896,-0.774 ; U1.AH19@-1.89,-0.769 U1.AG19@-1.75,-0.769
ASIC1_RSTB: J1.10 U1.AG8 U1.AH8 | length 3.7
  metal 2 w0.05: J1.10@-5.009,-0.254 -4.973,-0.218 -4.693,-0.218 -4.289,0.186 -2.782,0.186 -2.196,0.771 U1.AH8@-1.89,0.771 U1.AG8@-1.75,0.771
ASIC1_SCLK: J1.8 U1.AG6 U1.AH6 | length 4
  metal 2 w0.05: J1.8@-5.184,0.144 -5.128,0.2 -4.711,0.2 -4.46,0.451 -4.46,0.706 -4.114,1.051 U1.AH6@-1.89,1.051 U1.AG6@-1.75,1.051
ASIC1_SDIN: J1.9 U1.AG5 U1.AH5 | length 7.4
  metal 2 w0.05: J1.9@-8.442,-0.285 -6.535,-0.285 -5.904,0.346 -4.775,0.346 -4.589,0.533 -4.589,0.753 -4.15,1.191 U1.AH5@-1.89,1.191 U1.AG5@-1.75,1.191
ASIC1_SDOUT: J1.11 U1.AG7 U1.AH7 | length 7.4
  metal 2 w0.05: J1.11@-8.339,-0.656 -6.379,-0.656 -5.761,-0.038 -4.757,-0.038 -4.314,0.405 -4.314,0.701 -4.104,0.911 U1.AH7@-1.89,0.911 U1.AG7@-1.75,0.911
ASIC1_WCLK0: J1.16 U1.AG14 U1.AH14 | length 4
  metal 2 w0.06: J1.16@-5.184,-1.456 -3.5,-1.456 -2.113,-0.069 U1.AH14@-1.89,-0.069 U1.AG14@-1.75,-0.069
ASIC1_WCLK1: J1.18 U1.AG16 U1.AH16 | length 4.1
  metal 2 w0.06: J1.18@-5.184,-1.856 -3.549,-1.856 -2.042,-0.349 U1.AH16@-1.89,-0.349 U1.AG16@-1.75,-0.349
ASIC1_WCLK2: J1.20 U1.AG18 U1.AH18 | length 4.1
  metal 2 w0.06: J1.20@-5.184,-2.256 -3.608,-2.256 -1.981,-0.629 U1.AG18@-1.75,-0.629
ASIC1_WCLK3: J1.22 U1.AG20 U1.AH20 | length 4.2
  metal 2 w0.06: J1.22@-5.184,-2.656 -3.637,-2.656 U1.AH20@-1.89,-0.909 U1.AG20@-1.75,-0.909
DVDD_1V2: C5.1 C6.1 J1.6 pad.34@-1.994,0.196 pad.34@-1.994,0.214 pad.34@-1.994,0.232 pad.34@-1.994,1.456 pad.34@-1.994,1.474 pad.34@-1.994,1.492 pad.34@-1.994,-1.308 pad.34@-1.994,-1.326 pad.34@-1.994,-1.344 pad.34@-2.03,0.196 pad.34@-2.03,0.214 pad.34@-2.03,0.232 pad.34@-2.03,1.456 pad.34@-2.03,1.474 pad.34@-2.03,1.492 pad.34@-2.03,-1.308 pad.34@-2.03,-1.326 pad.34@-2.03,-1.344 pad.34@-2.012,0.196 pad.34@-2.012,0.214 pad.34@-2.012,0.232 pad.34@-2.012,1.456 pad.34@-2.012,1.474 pad.34@-2.012,1.492 pad.34@-2.012,-1.308 pad.34@-2.012,-1.326 pad.34@-2.012,-1.344 U1.AG3 U1.AG12 U1.AG23 U1.AH3 U1.AH12 U1.AH23 | length 7.5
  metal 2 w0.05: U1.AH23@-1.89,-1.329 U1.AG23@-1.75,-1.329 ; U1.AH3@-1.89,1.471 U1.AG3@-1.75,1.471
  metal 2 w0.08: pad.34@-2.031,1.474 U1.AG3@-1.753,1.474 ; pad.34@-2.03,-1.326 U1.AG23@-1.753,-1.326 ; pad.34@-2.012,0.214 pad.34@-1.994,0.214 -1.753,0.214 U1.AG12@-1.75,0.211
  metal1 w0.127: J1.6@-5.184,0.544 -4.029,0.544 C6.1@-3.98,0.495 -3.918,0.557 -2.273,0.557 -2.244,0.586 ; pad.34@-2.03,1.474 pad.34@-2.012,1.474 -2.015,1.471 -2.145,1.471 -2.244,1.372 -2.244,0.586 ; pad.34@-2.012,-1.326 pad.34@-2.03,-1.326 -2.11,-1.326 -2.113,-1.329 -2.244,-1.198 -2.244,0.214 ; pad.34@-2.012,0.214 pad.34@-2.03,0.214 -2.244,0.214 ; -2.244,0.214 -2.244,0.586
DVDD_1V2_BOT: C9.1 C10.1 J1.5 pad.34@-1.223,3.066 pad.34@-1.223,3.084 pad.34@-1.223,3.102 pad.34@-1.223,3.691 pad.34@-1.223,3.709 pad.34@-1.223,3.727 pad.34@-1.241,3.066 pad.34@-1.241,3.084 pad.34@-1.241,3.102 pad.34@-1.241,3.691 pad.34@-1.241,3.709 pad.34@-1.241,3.727 pad.34@-1.259,3.066 pad.34@-1.259,3.084 pad.34@-1.259,3.102 pad.34@-1.259,3.691 pad.34@-1.259,3.709 pad.34@-1.259,3.727 U1.A9 U1.A17 U1.B9 U1.B17 | length 19.6
  metal 2 w0.1: -1.269,3.038 1.967,3.038 2.445,2.56 2.445,0.678 2.398,0.631 U1.A9@1.89,0.631 U1.B9@1.75,0.631 ; pad.34@-1.241,3.084 pad.34@-1.223,3.084 ; pad.34@-1.241,3.709 pad.34@-1.223,3.709 2.253,3.709 3.555,2.407 3.555,0.501 2.566,-0.489 U1.A17@1.89,-0.489 U1.B17@1.75,-0.489
  metal1 w0.08: pad.34@-1.241,3.691 pad.34@-1.241,3.709
  metal1 w0.1: C10.1@-3.675,1.562 C10.1@-3.644,1.592 ; C10.1@-3.643,1.578 C9.1@-2.853,1.578 ; C9.1@-2.786,1.621 -2.278,1.621
  metal1 w0.127: -2.228,1.789 -1.243,2.774 -1.243,2.793 -1.241,2.795 pad.34@-1.241,3.066 ; pad.34@-1.241,3.084 pad.34@-1.241,3.102 pad.34@-1.241,3.691
DVSS: C5.2 C6.2 J1.14 J1.24 U1.AF1 U1.AF2 U1.AF3 U1.AF4 U1.AF5 U1.AF6 U1.AF7 U1.AF8 U1.AF9 U1.AF10 U1.AF11 U1.AF12 U1.AF13 U1.AF14 U1.AF15 U1.AF16 U1.AF17 U1.AF18 U1.AF19 U1.AF20 U1.AF21 U1.AF22 U1.AF23 U1.AF24 U1.AF25 U1.AF26 U1.AG1 U1.AG2 U1.AG10 U1.AG11 U1.AG21 U1.AG22 U1.AH1 U1.AH2 U1.AH10 U1.AH11 U1.AH21 U1.AH22 | length 8.8
  metal 2 w0.05: J1.14@-5.184,-1.056 -4.084,-1.056 -3.98,-0.952 C6.2@-3.98,-0.305
  metal 2 w0.08: C5.2@-3.125,-0.243 -2.68,-0.243 ; U1.AH22@-1.89,-1.189 U1.AG22@-1.75,-1.189 U1.AF22@-1.61,-1.189 ; U1.AH21@-1.89,-1.049 U1.AG21@-1.75,-1.049 U1.AF21@-1.61,-1.049 ; U1.AH10@-1.89,0.491 U1.AG10@-1.75,0.491 U1.AF10@-1.61,0.491 ; U1.AH2@-1.89,1.611 -1.75,1.611 U1.AF2@-1.61,1.611 ; U1.AH1@-1.89,1.751 U1.AG1@-1.75,1.751 U1.AF1@-1.61,1.751 U1.AF2@-1.61,1.611 ; -1.827,-1.842 -1.703,-1.842 U1.AF26@-1.61,-1.749 U1.AF25@-1.61,-1.609 U1.AF24@-1.61,-1.469 U1.AF23@-1.61,-1.329 U1.AF22@-1.61,-1.189 ; U1.AF22@-1.61,-1.189 U1.AF21@-1.61,-1.049 ; U1.AF21@-1.61,-1.049 U1.AF20@-1.61,-0.909 -1.61,-0.769 U1.AF18@-1.61,-0.629 U1.AF17@-1.61,-0.489 U1.AF16@-1.61,-0.349 U1.AF15@-1.61,-0.209 U1.AF14@-1.61,-0.069 U1.AF13@-1.61,0.071 U1.AF12@-1.61,0.211 U1.AF11@-1.61,0.351 U1.AF10@-1.61,0.491 ; U1.AF10@-1.61,0.491 U1.AF9@-1.61,0.631 U1.AF8@-1.61,0.771 U1.AF7@-1.61,0.911 U1.AF6@-1.61,1.051 U1.AF5@-1.61,1.191 U1.AF4@-1.61,1.331 U1.AF3@-1.61,1.471 U1.AF2@-1.61,1.611
  metal 2 w0.127: -2.68,-0.243 -2.086,0.351 U1.AH11@-1.89,0.351 U1.AG11@-1.75,0.351 -1.659,0.351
